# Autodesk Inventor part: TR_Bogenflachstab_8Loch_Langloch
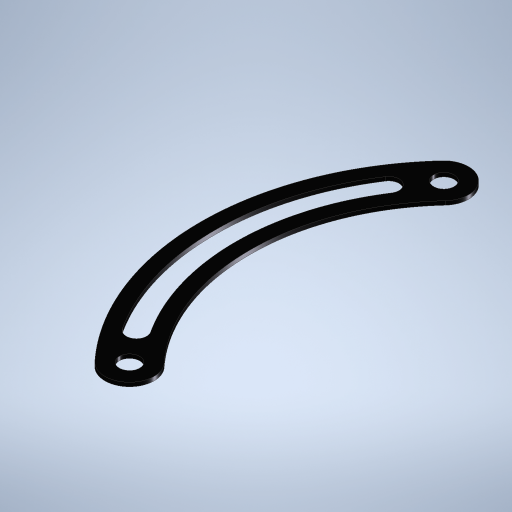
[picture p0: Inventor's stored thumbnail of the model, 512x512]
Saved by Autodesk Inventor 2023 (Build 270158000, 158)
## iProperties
Created: 2023-11
Part Number: TR_Bogenflachstab_8Loch_Langloch
Material: Edelstahl
Document SubType Name: Modeling
Designer: Admin
Density: 8 g/cm^3
Appearance: Halbpoliert
Author: Admin
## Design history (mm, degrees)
sketch "Skizze1"
  geometry: C1 r 2.075 at (0, 32); C2 r 2.075 at (0, -32); A1 r 52.21 centre (-34.71, 0) between (3.676, -35.389) and (3.676, 35.389); A2 r 42.21 centre (-34.71, 0) between (-3.676, -28.611) and (-3.676, 28.611); A3 r 5 centre (0, 32) between (3.676, 35.389) and (-3.676, 28.611); A4 r 5 centre (0, -32) between (-3.676, -28.611) and (3.676, -35.389); A5 r 47.21 centre (-34.71, 0) between (4.905, -25.68) and (4.905, 25.68); A6 r 49.285 centre (-34.71, 0) between (6.646, -26.809) and (6.646, 26.809); A7 r 45.135 centre (-34.71, 0) between (3.164, -24.551) and (3.164, 24.551); A8 r 2.075 centre (4.905, -25.68) between (3.164, -24.551) and (6.646, -26.809); A9 r 2.075 centre (4.905, 25.68) between (6.646, 26.809) and (3.164, 24.551); 5 further points
  constraints: 23 point on circle, 11 centre point, 8 tangent, 3 horizontal alignment, 3 vertical alignment, 2 coincident, 2 equal radius
  dimensions: "d0" = 10 distance of point (7.5, 0) point (17.5, 0) (= Einheitsmaß); "d1" = 64 distance of A4.centre A3.centre; "d2" = 17.5 horizontal distance of A3.centre point (17.5, 0); "d3" = 5 radius of A3 (= 0.5 x Einheitsmaß); "d5" = 4.15 diameter of C1 (= 2 x Radius); "d6" = 8 distance of A5.end A3.centre; "d7" = 5 distance of point (12.5, 0) point (17.5, 0) (= 0.5 x Einheitsmaß)
extrude "Extrusion1" new body sketch "Skizze1" distance "d8" = 0.8 (= Dicke); taper "d9" = 0 deg
node "Volumenkörper1"
other parameters: "Einheitsmaß" = 10 [user parameter; used in 3 equation terms], "Radius" = 2.075 [user parameter; used in 1 equation term], "Fasen" = 0.5 [user parameter], "Dicke" = 0.8 [user parameter; used in 1 equation term]
